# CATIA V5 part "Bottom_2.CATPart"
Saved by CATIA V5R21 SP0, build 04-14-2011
Part number: Part1.1.2
Material "Gold Metal": density 7860 kg/m3, Young's modulus 2e+11 Pa, Poisson ratio 0.266
Bounding box of the stored display mesh (mm): x 0 to 25, y -27.5 to 27.5, z -27.49 to 27.49
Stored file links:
  C:\Users\RIAD MAHAMUD PIASH\Desktop\Project\Bottom_2.CATPart
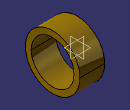
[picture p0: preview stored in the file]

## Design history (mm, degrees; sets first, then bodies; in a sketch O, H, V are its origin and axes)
Body1 (main body), material "Gold Metal"
  Sketch1 on yz-plane, origin (0, 0, 0), H (0, 1, 0), V (0, 0, 1)
    circle A1 centre (0, 0) radius 21.5
    circle A2 centre (0, 0) radius 27.5
    radius A2 = 27.5
    radius A1 = 21.5
  Pad1: profile Sketch1, direction (1, 0, 0), length 25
